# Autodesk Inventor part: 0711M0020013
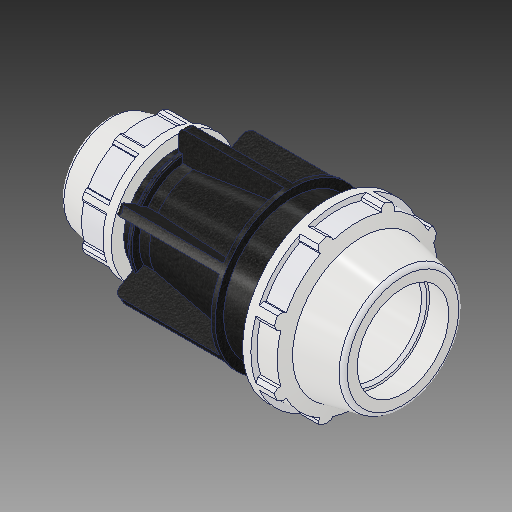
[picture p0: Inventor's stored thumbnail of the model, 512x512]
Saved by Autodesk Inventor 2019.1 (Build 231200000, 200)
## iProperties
Created: 2017-02
Part Number: 0711M0020013
Material: PVC-Piping
Description: PLASSON REDUCING COUPLER 2'' - 1 1/4''
Document SubType Name: Modeling
Designer: KIM
Mass: 92.6774 g
Surface Area: 199.44 cm^2
Volume: 66.1981 cm^3
Density: 1.4 g/cm^3
Appearance: PTFE
Author: KIM
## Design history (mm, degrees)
derived "0711M0.ipt"
feature "Solid1::0711M0.ipt"
tag "TaggingFeature1"
body "Solid1"
other parameters: "d2" = 60.1, "d4" = 16.08333, "d5" = 27.57143, "d7" = 113.03, "d9" = 27.57143, "d11" = 2.75714, "d12" = 90.424, "d13" = 120 deg, "d14" = 78.13, "d15" = 12 deg, "d16" = 101.727, "d18" = 3.005, "d19" = 35 deg, "d20" = 17.5 deg, "d21" = 105.1179, "d23" = 0, "d25" = 360 deg, "d27" = 2.2606, "d42" = 21.23, "d46" = 1.803, "d51" = 193, "d52" = 66.55172, "d53" = 12 deg, "d54" = 82.042, "d56" = 63.15, "d57" = 42.1, "d58" = 54.09, "d59" = 37.89, "d60" = 73.8378, "d61" = 65.6336, "d62" = 19.3, "d63" = 23.16, "d64" = 120 deg, "d65" = 82.042, "d68" = 13.78571, "d74" = 76.29906, "d75" = 35 deg, "d76" = 17.5 deg, "d78" = 0, "d80" = 360 deg, "d85" = 1.64084, "d88" = 0.842, "d93" = 58, "d94" = 79.121, "d97" = 3.47017, "d98" = 5.46947, "d99" = 0, "d100" = 4.5212, "d102" = 360 deg, "d104" = 2, "d106" = 0, "d107" = 5.46947, "d108" = 0, "d109" = 5.46947, "d110" = 0, "d_" = 60.1, "E_" = 113.03, "H_" = 193, "l_" = 82.042, "d_1" = 42.1, "E_1" = 82.042, "l_1" = 58, "d96" = 10.4105
